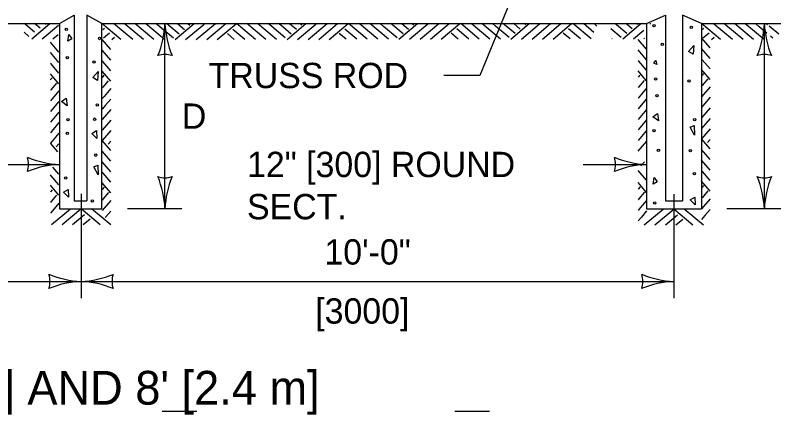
# Model space of a CAD drawing. Extents: x 49973.1 to 50021, y 49987.6 to 50015.4.
# Drawn here: x 50003.121 to 50004.917, y 49996.427 to 49997.374 of the extents above; entities that cross this region are included whole.
import ezdxf

# ---------------------------------------------------------------- set-up
doc = ezdxf.new("R2010")
doc.units = 0
for name, color, linetype in [('Level 1', 7, 'Continuous'), ('Level 2', 7, 'Continuous'), ('Level 3', 7, 'Continuous')]:
    doc.layers.add(name, color=color, linetype=linetype)

msp = doc.modelspace()

# ---------------------------------------------------------------- linework, layer by layer
at = {"layer": 'Level 1'}
for p, q in [((50003.2258, 49997.3541), (50003.2608, 49997.3738)), ((50003.2608, 49997.3739), (50003.2608, 49996.9341)), ((50003.2908, 49997.3739), (50003.2908, 49996.9341)), ((50003.3258, 49997.354), (50003.2908, 49997.3735)), ((50004.6158, 49997.3541), (50004.6607, 49997.3741)), ((50004.6608, 49997.3741), (50004.6608, 49996.9341)), ((50004.7008, 49997.3741), (50004.7008, 49996.9341)), ((50004.7458, 49997.3541), (50004.7011, 49997.3741)), ((50001.9258, 49997.3541), (50003.2258, 49997.3541)), ((50003.1451, 49997.3513), (50003.1418, 49997.354)), ((50003.1665, 49997.3334), (50003.1451, 49997.3513)), ((50003.1599, 49997.3179), (50003.2028, 49997.354)), ((50003.1799, 49997.3431), (50003.1668, 49997.354)), ((50003.1849, 49997.3179), (50003.2233, 49997.3501)), ((50003.1944, 49997.3518), (50003.1918, 49997.354)), ((50003.2235, 49997.3541), (50003.2258, 49997.3541)), ((50003.2258, 49997.3541), (50003.2258, 49996.915)), ((50003.3258, 49996.915), (50003.3258, 49997.354)), ((50003.3713, 49997.3159), (50003.3258, 49997.354)), ((50003.3258, 49997.354), (50004.6158, 49997.354)), ((50003.3995, 49997.3158), (50003.354, 49997.3539)), ((50003.4245, 49997.3158), (50003.3791, 49997.3539)), ((50003.4495, 49997.3158), (50003.404, 49997.3539)), ((50003.4745, 49997.3158), (50003.429, 49997.3539)), ((50003.4631, 49997.3463), (50003.4539, 49997.3539)), ((50003.4847, 49997.3492), (50003.479, 49997.3539)), ((50003.5093, 49997.3286), (50003.4847, 49997.3492)), ((50003.4995, 49997.3158), (50003.5448, 49997.3539)), ((50003.5061, 49997.3522), (50003.504, 49997.3539)), ((50003.5218, 49997.3391), (50003.5061, 49997.3522)), ((50003.5245, 49997.3158), (50003.5675, 49997.3519)), ((50003.5295, 49997.3535), (50003.529, 49997.3539)), ((50003.5345, 49997.3493), (50003.5295, 49997.3535)), ((50003.5495, 49997.3158), (50003.5948, 49997.3539)), ((50003.5675, 49997.3519), (50003.5698, 49997.3539)), ((50003.5745, 49997.3158), (50003.6198, 49997.3539)), ((50003.5995, 49997.3158), (50003.6448, 49997.3539)), ((50003.6896, 49997.3163), (50003.6448, 49997.3539)), ((50003.7146, 49997.3163), (50003.6696, 49997.3539)), ((50003.7396, 49997.3163), (50003.6946, 49997.3539)), ((50003.7282, 49997.3468), (50003.7196, 49997.3539)), ((50003.7498, 49997.3497), (50003.7447, 49997.3539)), ((50003.7744, 49997.3291), (50003.7498, 49997.3497)), ((50003.7646, 49997.3163), (50003.8093, 49997.3539)), ((50003.7712, 49997.3527), (50003.7697, 49997.3539)), ((50003.7869, 49997.3396), (50003.7712, 49997.3527)), ((50003.7896, 49997.3163), (50003.8326, 49997.3524)), ((50003.7996, 49997.3498), (50003.7946, 49997.354)), ((50003.8146, 49997.3163), (50003.8593, 49997.3539)), ((50003.8326, 49997.3524), (50003.8343, 49997.3539)), ((50003.8396, 49997.3163), (50003.8843, 49997.3539)), ((50003.8646, 49997.3163), (50003.9093, 49997.3539)), ((50003.9547, 49997.3168), (50003.9104, 49997.3539)), ((50003.9797, 49997.3168), (50003.9353, 49997.3539)), ((50004.0047, 49997.3168), (50003.9603, 49997.3539)), ((50003.9933, 49997.3473), (50003.9853, 49997.3539)), ((50004.0149, 49997.3502), (50004.0104, 49997.3539)), ((50004.0395, 49997.3296), (50004.0149, 49997.3502)), ((50004.0297, 49997.3168), (50004.0738, 49997.3539)), ((50004.0363, 49997.3532), (50004.0354, 49997.3539)), ((50004.052, 49997.3401), (50004.0363, 49997.3532)), ((50004.0547, 49997.3168), (50004.0977, 49997.3529)), ((50004.0647, 49997.3503), (50004.0604, 49997.3539)), ((50004.0797, 49997.3168), (50004.1238, 49997.3539)), ((50004.0977, 49997.3529), (50004.0988, 49997.3539)), ((50004.1047, 49997.3168), (50004.1488, 49997.3539)), ((50004.1297, 49997.3168), (50004.1738, 49997.3539)), ((50004.2198, 49997.3173), (50004.1761, 49997.3539)), ((50004.2448, 49997.3173), (50004.201, 49997.3539)), ((50004.2698, 49997.3173), (50004.226, 49997.3539)), ((50004.2584, 49997.3478), (50004.251, 49997.3539)), ((50004.28, 49997.3507), (50004.2761, 49997.3539)), ((50004.3046, 49997.3301), (50004.28, 49997.3507)), ((50004.2948, 49997.3173), (50004.3383, 49997.3539)), ((50004.3014, 49997.3537), (50004.3011, 49997.3539)), ((50004.3171, 49997.3406), (50004.3014, 49997.3537)), ((50004.3198, 49997.3173), (50004.3628, 49997.3534)), ((50004.3298, 49997.3508), (50004.3261, 49997.3539)), ((50004.3448, 49997.3173), (50004.3883, 49997.3539)), ((50004.3628, 49997.3534), (50004.3633, 49997.3539)), ((50004.3698, 49997.3173), (50004.4133, 49997.3539)), ((50004.3948, 49997.3173), (50004.4383, 49997.3539)), ((50004.4849, 49997.3178), (50004.4418, 49997.3539)), ((50004.4849, 49997.3178), (50004.4418, 49997.3539)), ((50004.4915, 49997.3331), (50004.4667, 49997.3539)), ((50004.4986, 49997.3481), (50004.4917, 49997.3539)), ((50004.5451, 49997.3512), (50004.5418, 49997.3539)), ((50004.5697, 49997.3306), (50004.5451, 49997.3512)), ((50004.5599, 49997.3178), (50004.6028, 49997.3539)), ((50004.5822, 49997.3411), (50004.5668, 49997.3539)), ((50004.5949, 49997.3513), (50004.5918, 49997.3539)), ((50004.6158, 49997.3541), (50004.6158, 49996.915)), ((50004.6235, 49997.354), (50004.6258, 49997.354)), ((50004.7458, 49997.3541), (50004.7458, 49996.915)), ((50004.7913, 49997.316), (50004.7458, 49997.3541)), ((50004.7458, 49997.3541), (50005.0266, 49997.3541)), ((50004.8195, 49997.3159), (50004.774, 49997.354)), ((50004.8445, 49997.3159), (50004.7991, 49997.354)), ((50004.8695, 49997.3159), (50004.824, 49997.354)), ((50004.8945, 49997.3159), (50004.849, 49997.354)), ((50004.8831, 49997.3464), (50004.8739, 49997.354)), ((50004.9027, 49997.351), (50004.899, 49997.354)), ((50003.1534, 49997.3233), (50003.1417, 49997.3332)), ((50003.3284, 49997.3401), (50003.3319, 49997.343)), ((50003.3296, 49997.3201), (50003.344, 49997.3321)), ((50003.4954, 49997.3192), (50003.4631, 49997.3463)), ((50003.6646, 49997.3163), (50003.6362, 49997.3401)), ((50003.7605, 49997.3197), (50003.7282, 49997.3468)), ((50003.9297, 49997.3168), (50003.9013, 49997.3406)), ((50004.0256, 49997.3202), (50003.9933, 49997.3473)), ((50004.1948, 49997.3173), (50004.1664, 49997.3411)), ((50004.2907, 49997.3207), (50004.2584, 49997.3478)), ((50004.4349, 49997.3178), (50004.4186, 49997.3315)), ((50004.4599, 49997.3178), (50004.4315, 49997.3416)), ((50004.5558, 49997.3212), (50004.5315, 49997.3416)), ((50004.5849, 49997.3178), (50004.6095, 49997.3384)), ((50004.7484, 49997.3402), (50004.7519, 49997.3431)), ((50004.7496, 49997.3202), (50004.764, 49997.3322)), ((50004.9009, 49997.3315), (50004.8831, 49997.3464)), ((50004.9293, 49997.3287), (50004.9067, 49997.3476)), ((50003.2099, 49997.3179), (50003.2223, 49997.3283)), ((50003.3469, 49997.2922), (50003.327, 49997.3159)), ((50003.3495, 49997.3158), (50003.3563, 49997.3215)), ((50003.6396, 49997.3163), (50003.6233, 49997.33)), ((50003.9047, 49997.3168), (50003.8884, 49997.3305)), ((50004.1698, 49997.3173), (50004.1535, 49997.331)), ((50004.5349, 49997.3178), (50004.5339, 49997.3186)), ((50004.6158, 49997.2931), (50004.5961, 49997.3165)), ((50004.6099, 49997.3178), (50004.6112, 49997.3189)), ((50004.7664, 49997.2963), (50004.7465, 49997.32)), ((50004.7695, 49997.3159), (50004.7763, 49997.3216)), ((50004.9154, 49997.3193), (50004.9098, 49997.324)), ((50003.224, 49997.2863), (50003.2041, 49997.31)), ((50003.224, 49997.2613), (50003.2041, 49997.285)), ((50003.3469, 49997.2672), (50003.327, 49997.2909)), ((50004.6158, 49997.2681), (50004.5961, 49997.2915)), ((50004.7664, 49997.2713), (50004.7465, 49997.295)), ((50003.2056, 49997.2583), (50003.2041, 49997.26)), ((50003.3285, 49997.2642), (50003.327, 49997.2659)), ((50003.3469, 49997.2422), (50003.3285, 49997.2642)), ((50004.5976, 49997.2648), (50004.5961, 49997.2665)), ((50004.6158, 49997.2431), (50004.5976, 49997.2648)), ((50004.748, 49997.2683), (50004.7465, 49997.27)), ((50004.7664, 49997.2463), (50004.748, 49997.2683)), ((50003.224, 49997.2363), (50003.2056, 49997.2583)), ((50004.6158, 49997.2181), (50004.5961, 49997.2415)), ((50004.7664, 49997.2213), (50004.7465, 49997.245)), ((50003.2082, 49997.2253), (50003.204, 49997.2203)), ((50003.224, 49997.2113), (50003.2041, 49997.235)), ((50003.3311, 49997.2312), (50003.3269, 49997.2262)), ((50003.3469, 49997.2172), (50003.327, 49997.2409)), ((50004.6002, 49997.2318), (50004.596, 49997.2268)), ((50004.7506, 49997.2353), (50004.7464, 49997.2303)), ((50003.2184, 49997.2126), (50003.2053, 49997.1969)), ((50003.3413, 49997.2185), (50003.3282, 49997.2028)), ((50004.6104, 49997.2191), (50004.5973, 49997.2034)), ((50004.7477, 49997.2069), (50004.7465, 49997.2054)), ((50004.7608, 49997.2226), (50004.7477, 49997.2069)), ((50003.2053, 49997.1969), (50003.2041, 49997.1954)), ((50003.224, 49997.1942), (50003.2083, 49997.1755)), ((50003.3282, 49997.2028), (50003.327, 49997.2013)), ((50003.3469, 49997.2001), (50003.3312, 49997.1814)), ((50004.5973, 49997.2034), (50004.5961, 49997.2019)), ((50004.6158, 49997.2005), (50004.6003, 49997.182)), ((50004.7664, 49997.2042), (50004.7507, 49997.1855)), ((50003.2083, 49997.1755), (50003.2041, 49997.1704)), ((50003.3312, 49997.1814), (50003.327, 49997.1763)), ((50003.3469, 49997.175), (50003.3341, 49997.1598)), ((50004.6003, 49997.182), (50004.5961, 49997.1769)), ((50004.6158, 49997.1754), (50004.6032, 49997.1604)), ((50004.7507, 49997.1855), (50004.7465, 49997.1804)), ((50004.7664, 49997.1791), (50004.7536, 49997.1639)), ((50003.2112, 49997.1539), (50003.2041, 49997.1453)), ((50003.224, 49997.1691), (50003.2112, 49997.1539)), ((50003.3341, 49997.1598), (50003.327, 49997.1512)), ((50004.6032, 49997.1604), (50004.5961, 49997.1518)), ((50004.7536, 49997.1639), (50004.7465, 49997.1553)), ((50004.7664, 49997.1541), (50004.7465, 49997.1303)), ((50003.224, 49997.1441), (50003.2041, 49997.1203)), ((50003.3469, 49997.15), (50003.327, 49997.1262)), ((50004.6158, 49997.1504), (50004.5961, 49997.1268)), ((50003.224, 49997.1191), (50003.2041, 49997.0953)), ((50003.3469, 49997.125), (50003.327, 49997.1012)), ((50004.6158, 49997.1254), (50004.5961, 49997.1018)), ((50004.7664, 49997.1291), (50004.7465, 49997.1053)), ((50003.3469, 49997.1001), (50003.327, 49997.0764)), ((50004.6158, 49997.1005), (50004.5961, 49997.077)), ((50004.7664, 49997.1042), (50004.7465, 49997.0805)), ((50003.224, 49997.0942), (50003.2041, 49997.0705)), ((50004.7664, 49997.0568), (50004.7465, 49997.0805)), ((50003.2214, 49997.0499), (50003.2041, 49997.0705)), ((50003.224, 49997.0691), (50003.2179, 49997.0619)), ((50003.3469, 49997.0527), (50003.327, 49997.0764)), ((50003.3469, 49997.075), (50003.3408, 49997.0678)), ((50004.6158, 49997.0754), (50004.5956, 49997.0516)), ((50004.7664, 49997.0791), (50004.7603, 49997.0719)), ((50003.3469, 49997.0277), (50003.327, 49997.0514)), ((50004.7664, 49997.0318), (50004.7465, 49997.0555)), ((50003.3469, 49997.0027), (50003.327, 49997.0264)), ((50004.6109, 49997.0263), (50004.6026, 49997.0164)), ((50004.7664, 49997.0068), (50004.7465, 49997.0305)), ((50003.224, 49996.9968), (50003.2101, 49997.0134)), ((50003.2061, 49996.9932), (50003.2041, 49996.9955)), ((50003.224, 49996.9718), (50003.2061, 49996.9932)), ((50003.329, 49996.9991), (50003.327, 49997.0014)), ((50003.3469, 49996.9777), (50003.329, 49996.9991)), ((50004.6158, 49996.9824), (50004.5961, 49997.0058)), ((50004.7485, 49997.0032), (50004.7465, 49997.0055)), ((50004.7664, 49996.9818), (50004.7485, 49997.0032)), ((50003.3469, 49996.9527), (50003.327, 49996.9764)), ((50004.6158, 49996.9536), (50004.5961, 49996.977)), ((50004.7664, 49996.9568), (50004.7465, 49996.9805)), ((50003.224, 49996.9468), (50003.2041, 49996.9705)), ((50003.2045, 49996.9552), (50003.2041, 49996.9547)), ((50003.2087, 49996.9602), (50003.2045, 49996.9552)), ((50003.3274, 49996.9611), (50003.327, 49996.9606)), ((50003.3316, 49996.9661), (50003.3274, 49996.9611)), ((50004.5965, 49996.9617), (50004.5961, 49996.9612)), ((50004.6007, 49996.9667), (50004.5965, 49996.9617)), ((50004.6109, 49996.954), (50004.5978, 49996.9383)), ((50004.7469, 49996.9652), (50004.7465, 49996.9647)), ((50004.7511, 49996.9702), (50004.7469, 49996.9652)), ((50004.7613, 49996.9575), (50004.7482, 49996.9418)), ((50003.2189, 49996.9475), (50003.2058, 49996.9318)), ((50003.3287, 49996.9377), (50003.327, 49996.9356)), ((50003.3418, 49996.9534), (50003.3287, 49996.9377)), ((50004.5978, 49996.9383), (50004.5961, 49996.9362)), ((50004.7482, 49996.9418), (50004.7465, 49996.9397)), ((50004.7664, 49996.9385), (50004.7512, 49996.9204)), ((50003.2058, 49996.9318), (50003.2041, 49996.9297)), ((50003.224, 49996.9285), (50003.2088, 49996.9104)), ((50003.2608, 49996.9341), (50003.2908, 49996.9341)), ((50003.3469, 49996.9344), (50003.3317, 49996.9163)), ((50004.6158, 49996.9348), (50004.6008, 49996.9169)), ((50004.6608, 49996.9341), (50004.7008, 49996.9341)), ((50004.7512, 49996.9204), (50004.7465, 49996.9147)), ((50003.2088, 49996.9104), (50003.2041, 49996.9047)), ((50003.2068, 49996.8775), (50003.2517, 49996.915)), ((50003.2258, 49996.915), (50003.3258, 49996.915)), ((50003.2318, 49996.8775), (50003.2765, 49996.915)), ((50003.2568, 49996.8775), (50003.2852, 49996.9013)), ((50003.3219, 49996.877), (50003.2767, 49996.915)), ((50003.3469, 49996.877), (50003.3017, 49996.915)), ((50003.3317, 49996.9163), (50003.327, 49996.9106)), ((50003.3469, 49996.9093), (50003.3346, 49996.8947)), ((50004.6008, 49996.9169), (50004.5961, 49996.9112)), ((50004.616, 49996.9099), (50004.6037, 49996.8953)), ((50004.6106, 49996.8767), (50004.6556, 49996.9143)), ((50004.6158, 49996.915), (50004.7458, 49996.915)), ((50004.6356, 49996.8767), (50004.6804, 49996.9143)), ((50004.6606, 49996.8767), (50004.689, 49996.9005)), ((50004.7257, 49996.8762), (50004.6804, 49996.9143)), ((50004.7507, 49996.8762), (50004.7054, 49996.9143)), ((50004.7664, 49996.9134), (50004.7541, 49996.8988)), ((50003.2818, 49996.8775), (50003.2981, 49996.8912)), ((50003.3346, 49996.8947), (50003.3338, 49996.8937)), ((50004.6037, 49996.8953), (50004.5961, 49996.8861)), ((50004.6856, 49996.8767), (50004.7019, 49996.8904)), ((50004.7541, 49996.8988), (50004.7465, 49996.8896))]:
    msp.add_line(p, q, dxfattribs=at)
for points in [[(50003.2457, 49997.3121), (50003.2478, 49997.3278), (50003.2546, 49997.3176)], [(50004.7156, 49997.2878), (50004.728, 49997.3022), (50004.7266, 49997.281)], [(50004.6333, 49997.2604), (50004.6381, 49997.2666), (50004.6401, 49997.257)], [(50003.3048, 49997.2258), (50003.3172, 49997.2402), (50003.3158, 49997.219)], [(50003.2308, 49997.169), (50003.2418, 49997.1772), (50003.2439, 49997.1593)], [(50004.6312, 49997.1328), (50004.6422, 49997.141), (50004.6443, 49997.1231)], [(50003.3025, 49997.0934), (50003.3135, 49997.1003), (50003.3142, 49997.0818)], [(50004.719, 49997.1087), (50004.7286, 49997.1122), (50004.7293, 49997.0895)], [(50003.307, 49997.0144), (50003.3166, 49997.0179), (50003.3173, 49996.9952)], [(50004.6319, 49996.9736), (50004.634, 49996.9893), (50004.6408, 49996.9791)], [(50003.2354, 49996.9539), (50003.2464, 49996.9608), (50003.2471, 49996.9423)], [(50004.7197, 49996.9358), (50004.7307, 49996.9427), (50004.7314, 49996.9242)]]:
    msp.add_lwpolyline(points, close=True, dxfattribs=at)
for centre in [(50004.634, 49997.3488), (50003.2417, 49997.3404), (50004.7218, 49997.3447), (50003.3205, 49997.3185), (50004.6532, 49997.3049), (50003.2442, 49997.2732), (50003.3076, 49997.2629), (50004.6374, 49997.2226), (50004.7163, 49997.2178), (50004.6408, 49997.1828), (50003.3153, 49997.1609), (50003.2455, 49997.126), (50003.3088, 49997.1273), (50004.73, 49997.1258), (50004.6333, 49997.0997), (50003.2442, 49997.0937), (50003.3114, 49997.042), (50004.6443, 49997.0531), (50004.7198, 49997.0524), (50003.2404, 49996.9877), (50004.7294, 49996.9982), (50003.3037, 49996.9335), (50004.6354, 49996.9289)]:
    msp.add_circle(centre, 0.00279, dxfattribs=at)
at = {"layer": 'Level 2'}
for p, q in [((50003.5509, 49996.4347), (50003.469, 49996.4347)), ((50004.2438, 49996.4347), (50004.1619, 49996.4347))]:
    msp.add_line(p, q, dxfattribs=at)
at = {"layer": 'Level 3'}
for p, q in [((50004.3186, 49997.4678), (50004.221, 49997.2308)), ((50003.4755, 49996.915), (50003.4755, 49997.354)), ((50004.895, 49996.915), (50004.895, 49997.3541)), ((50004.221, 49997.2308), (50004.1361, 49997.2308)), ((50003.065, 49997.02), (50003.2258, 49997.02)), ((50004.4661, 49997.02), (50004.6158, 49997.02)), ((50003.2767, 49996.9501), (50003.2767, 49996.7027)), ((50004.6805, 49996.9496), (50004.6805, 49996.7028)), ((50003.5155, 49996.915), (50003.3869, 49996.915)), ((50004.935, 49996.915), (50004.8064, 49996.915)), ((50001.8758, 49996.7427), (50003.2767, 49996.7427)), ((50003.2767, 49996.7427), (50004.6805, 49996.7427)), ((50004.6805, 49996.7427), (50004.6805, 49996.7027))]:
    msp.add_line(p, q, dxfattribs=at)
for centre, radius, start, end in [((50003.2534, 49997.3632), 0.2223, 337.456, 357.6395), ((50003.7082, 49997.3655), 0.233, 182.8273, 202.0772), ((50004.6729, 49997.3633), 0.2223, 337.456, 357.6395), ((50005.1277, 49997.3656), 0.233, 182.8273, 202.0772), ((50003.4755, 49997.2258), 0.0548, 72.1388, 107.8612), ((50004.895, 49997.2259), 0.0548, 72.1388, 107.8612), ((50003.235, 49997.2422), 0.2223, 247.456, 267.6395), ((50003.0976, 49997.02), 0.0548, 342.1388, 17.8612), ((50004.625, 49997.2422), 0.2223, 247.456, 267.6395), ((50004.4876, 49997.02), 0.0548, 342.1388, 17.8612), ((50003.2373, 49996.7873), 0.233, 92.8273, 112.0772), ((50004.6273, 49996.7873), 0.233, 92.8273, 112.0772), ((50003.4755, 49997.0432), 0.0548, 252.1388, 287.8612), ((50003.2428, 49996.9035), 0.233, 2.8273, 22.0772), ((50003.6976, 49996.9059), 0.2223, 157.456, 177.6395), ((50004.895, 49997.0432), 0.0548, 252.1388, 287.8612), ((50004.6623, 49996.9035), 0.233, 2.8273, 22.0772), ((50005.1171, 49996.9059), 0.2223, 157.456, 177.6395), ((50003.2859, 49996.9649), 0.2223, 247.456, 267.6395), ((50003.1485, 49996.7427), 0.0548, 342.1388, 17.8612), ((50003.2652, 49996.9754), 0.233, 272.8273, 292.0772), ((50003.4049, 49996.7427), 0.0548, 162.1388, 197.8612), ((50004.6897, 49996.9649), 0.2223, 247.456, 267.6395), ((50004.5523, 49996.7427), 0.0548, 342.1388, 17.8612), ((50003.2882, 49996.51), 0.233, 92.8273, 112.0772), ((50003.2675, 49996.5206), 0.2223, 67.456, 87.6395), ((50004.692, 49996.51), 0.233, 92.8273, 112.0772)]:
    msp.add_arc(centre, radius, start, end, dxfattribs=at)

# ---------------------------------------------------------------- texts
at = {"layer": 'Level 2'}
for s, height, p in [('TRUSS ROD', 0.06, (50003.5788, 49997.2008)), ('D', 0.06, (50003.5155, 49997.1045)), ('12" [300] ROUND', 0.06, (50003.6698, 49996.99)), ('SECT.', 0.06, (50003.6698, 49996.89)), ('10\'-0"', 0.06, (50003.8532, 49996.7827)), ('[3000]', 0.06, (50003.8314, 49996.6427)), ("CHAIN LINK FENCE - 6' [1.8 m] AND 8' [2.4 m]", 0.08, (50001.5955, 49996.4507))]:
    msp.add_text(s, height=height, dxfattribs=at).set_placement(p)

doc.saveas('drawing.dxf')
